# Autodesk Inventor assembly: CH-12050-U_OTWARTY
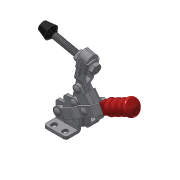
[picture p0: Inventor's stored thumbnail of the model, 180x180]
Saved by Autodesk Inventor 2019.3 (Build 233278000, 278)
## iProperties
Company: Î¢ÈíÖÐ¹ú
Created: 2015-08
Part Number: CH-12050-U_OTWARTY
Material: Ogólny
Description: STEP AP203
Document SubType Name: Assembly
Designer: CADENGINEERING4
Sending System: SolidWorks 2012
Preprocessor: SwSTEP 2.0
Title: CH-12050-U.STEP
Author: Î¢ÈíÓÃ»§
Revision Number: ÈÎºÎ
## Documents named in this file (11)
- D:\Vault_2016\Projekty\NASZ KATALOG\CLAMPTEK\STRONA\Vertical toggle clamp\CH-12050-U\CH-12050-U_OTWARTY.iam
- D:\Vault_2016\Projekty\NASZ KATALOG\CLAMPTEK\STEP FILES\Vertical toggle clamp\CH-12050-U\CH-12050-01 FLANGED BASE.ipt
- D:\Vault_2016\Projekty\NASZ KATALOG\CLAMPTEK\STEP FILES\Vertical toggle clamp\CH-12050-U\CH-12050-04 CONNECTING-PLATE.ipt
- D:\Vault_2016\Projekty\NASZ KATALOG\CLAMPTEK\STEP FILES\Vertical toggle clamp\CH-12050-U\CH-12050-03 STRAIGHT HANDLE.ipt
- D:\Vault_2016\Projekty\NASZ KATALOG\CLAMPTEK\STEP FILES\Vertical toggle clamp\CH-12050-U\CH-12050-07.ipt
- D:\Vault_2016\Projekty\NASZ KATALOG\CLAMPTEK\STEP FILES\Vertical toggle clamp\CH-12050-U\CH-12050-06.ipt
- D:\Vault_2016\Projekty\NASZ KATALOG\CLAMPTEK\STEP FILES\Vertical toggle clamp\CH-12050-U\CH-FW-140.ipt
- D:\Vault_2016\Projekty\NASZ KATALOG\CLAMPTEK\STEP FILES\Vertical toggle clamp\CH-12050-U\CH-12050-05.ipt
- D:\Vault_2016\Projekty\NASZ KATALOG\CLAMPTEK\STEP FILES\Vertical toggle clamp\CH-12050-U\CH-12050-U-02 U-BAR.ipt
- D:\Vault_2016\Projekty\NASZ KATALOG\CLAMPTEK\STEP FILES\Vertical toggle clamp\CH-12050-U\CH-FC-14134 Nut.ipt
- D:\Vault_2016\Projekty\NASZ KATALOG\CLAMPTEK\STEP FILES\Vertical toggle clamp\CH-12050-U\CH-FC-14134 SPINDLE SUPPLIED.ipt
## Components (14 placed, 10 different names)
1. CH-12050-01 FLANGED BASE_1
2. CH-12050-04 CONNECTING-PLATE:2 — Zestawiające:4, Zestawiające:5, Zestawiające:7, Zestawiające:9, Zestawiające:12, Zestawiające:13, Zestawiające:15, Zestawiające:16
3. CH-12050-03 STRAIGHT HANDLE:2 — Zestawiające:1, Zestawiające:2, Zestawiające:3, Zestawiające:10, Zestawiające:11, Zestawiające:14, Zestawiające:16, Zestawiające:27, Zestawiające:28, Zestawiające:29
4. CH-12050-07:3 — Zestawiające:4, Zestawiające:5, Zestawiające:6, Zestawiające:7
5. CH-12050-07:4 — Zestawiające:8, Zestawiające:9
6. CH-12050-06:3 — Zestawiające:1, Zestawiające:2, Zestawiające:3
7. CH-12050-06:4 — Zestawiające:10, Zestawiające:11, Zestawiające:12, Zestawiające:13, Zestawiające:14
8. CH-FW-140:3 — Zestawiające:19, Zestawiające:21, Zestawiające:24, Równoległe:1, Zestawiające:25
9. CH-FW-140:4 — Zestawiające:20, Zestawiające:22, Zestawiające:23, Równoległe:1
10. CH-12050-05:2 — Zestawiające:27, Zestawiające:28, Zestawiające:29
11. CH-12050-U-02 U-BAR:2 — Zestawiające:6, Zestawiające:8, Zestawiające:15, Zestawiające:21, Zestawiające:22, Zestawiające:25, Zestawiające:26
12. CH-FC-14134 Nut:3 — Zestawiające:18, Zestawiające:19, Zestawiające:20, Zestawiające:24, Zestawiające:26
13. CH-FC-14134 SPINDLE SUPPLIED:2 — Zestawiające:17
14. CH-FC-14134 Nut:4 — Zestawiające:17, Zestawiające:18, Zestawiające:23
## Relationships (30: Mate 29, Flush 1)
- Zestawiające:1 [Mate]: CH-12050-03 STRAIGHT HANDLE:2 ↔ CH-12050-06:3
- Zestawiające:2 [Mate]: CH-12050-03 STRAIGHT HANDLE:2 ↔ CH-12050-06:3
- Zestawiające:3 [Mate]: CH-12050-03 STRAIGHT HANDLE:2 ↔ CH-12050-06:3
- Zestawiające:4 [Mate]: CH-12050-04 CONNECTING-PLATE:2 ↔ CH-12050-07:3
- Zestawiające:5 [Mate]: CH-12050-04 CONNECTING-PLATE:2 ↔ CH-12050-07:3
- Zestawiające:6 [Mate]: CH-12050-07:3 ↔ CH-12050-U-02 U-BAR:2
- Zestawiające:7 [Mate]: CH-12050-04 CONNECTING-PLATE:2 ↔ CH-12050-07:3
- Zestawiające:8 [Mate]: CH-12050-07:4 ↔ CH-12050-U-02 U-BAR:2
- Zestawiające:9 [Mate]: CH-12050-04 CONNECTING-PLATE:2 ↔ CH-12050-07:4
- Zestawiające:10 [Mate]: CH-12050-03 STRAIGHT HANDLE:2 ↔ CH-12050-06:4
- Zestawiające:11 [Mate]: CH-12050-03 STRAIGHT HANDLE:2 ↔ CH-12050-06:4
- Zestawiające:12 [Mate]: CH-12050-04 CONNECTING-PLATE:2 ↔ CH-12050-06:4
- Zestawiające:13 [Mate]: CH-12050-04 CONNECTING-PLATE:2 ↔ CH-12050-06:4
- Zestawiające:14 [Mate]: CH-12050-03 STRAIGHT HANDLE:2 ↔ CH-12050-06:4
- Zestawiające:15 [Mate]: CH-12050-04 CONNECTING-PLATE:2 ↔ CH-12050-U-02 U-BAR:2
- Zestawiające:16 [Mate]: CH-12050-04 CONNECTING-PLATE:2 ↔ CH-12050-03 STRAIGHT HANDLE:2
- Zestawiające:17 [Mate]: CH-FC-14134 SPINDLE SUPPLIED:2 ↔ CH-FC-14134 Nut:4
- Zestawiające:18 [Mate]: CH-FC-14134 Nut:3 ↔ CH-FC-14134 Nut:4
- Zestawiające:19 [Mate]: CH-FW-140:3 ↔ CH-FC-14134 Nut:3
- Zestawiające:20 [Mate]: CH-FW-140:4 ↔ CH-FC-14134 Nut:3
- Zestawiające:21 [Mate]: CH-FW-140:3 ↔ CH-12050-U-02 U-BAR:2
- Zestawiające:22 [Mate]: CH-FW-140:4 ↔ CH-12050-U-02 U-BAR:2
- Zestawiające:23 [Mate]: CH-FW-140:4 ↔ CH-FC-14134 Nut:4
- Zestawiające:24 [Mate]: CH-FW-140:3 ↔ CH-FC-14134 Nut:3
- Równoległe:1 [Flush]: CH-FW-140:3 ↔ CH-FW-140:4
- Zestawiające:25 [Mate]: CH-FW-140:3 ↔ CH-12050-U-02 U-BAR:2
- Zestawiające:26 [Mate]: CH-12050-U-02 U-BAR:2 ↔ CH-FC-14134 Nut:3
- Zestawiające:27 [Mate]: CH-12050-03 STRAIGHT HANDLE:2 ↔ CH-12050-05:2
- Zestawiające:28 [Mate]: CH-12050-03 STRAIGHT HANDLE:2 ↔ CH-12050-05:2
- Zestawiające:29 [Mate]: CH-12050-03 STRAIGHT HANDLE:2 ↔ CH-12050-05:2
